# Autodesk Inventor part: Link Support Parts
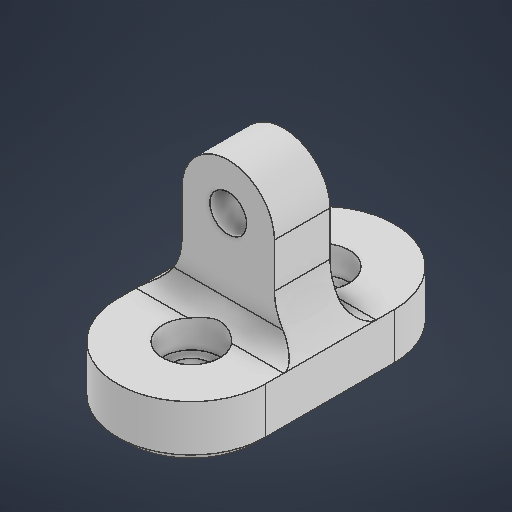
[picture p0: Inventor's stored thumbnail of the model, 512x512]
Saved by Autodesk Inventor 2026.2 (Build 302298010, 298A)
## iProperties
Created: 2026-05
Part Number: Link Support Parts
Material: 일반
Document SubType Name: Modeling
Designer: work
Density: 1 g/cm^3
Appearance: 기본값
Author: work
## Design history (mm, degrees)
sketch "스케치1"
  geometry: L1 (0, 7)-(0, -7); L2 (0, 7)-(0, -7); L3 (-8, 7)-(-8, -7); L4 (8, -7)-(8, 7); C1 r 2 at (0, 7); C2 r 2 at (0, -7); A1 r 8 centre (0, 7) between (8, 7) and (-8, 7); A2 r 8 centre (0, -7) between (-8, -7) and (8, -7); 2 further points
  constraints: 10 end point, 4 centre point, 4 point on circle, 4 tangent, 2 coincident, 2 equal length, 2 midpoint, 1 vertical
  dimensions: "d0" = 14 distance of L1.start L1.end; "d1" = 4 diameter of C1; "d2" = 4 diameter of C2; "d3" = 8 radius of A2
extrude "돌출1" new body sketch "스케치1" distance "d4" = 6; taper "d5" = 0 deg
sketch "스케치2"
  geometry: C1 r 2 at (0, -7) reference; C2 r 2 at (0, 7) reference; 3 further points
  constraints: 2 coincident
hole "구멍1" sketch "스케치2" at (0, -7), (0, 7) diameter "d6" = 4; stored, may be unused: countersink angle "d10" = 90 deg, drill point angle "d12" = 0 deg; dims "d7" = 5, "d8" = 6.2, "d9" = 3, "d11" = 5
sketch "스케치3"
  geometry: L1 (8, 6)-(-8, 6) reference; L2 (0, 6)-(0, 16); L3 (5, 6)-(5, 16); L4 (-5, 16)-(-5, 6); C1 r 2 at (0, 16); A1 r 5 centre (0, 6) between (-5, 6) and (5, 6); A2 r 5 centre (0, 16) between (5, 16) and (-5, 16); 2 further points
  constraints: 8 end point, 4 point on circle, 4 tangent, 3 centre point, 2 midpoint, 1 coincident, 1 parallel, 1 perpendicular
  dimensions: "d13" = 4 diameter of C1; "d14" = 10 distance of L2.start L2.end; "d15" = 5 radius of A2
extrude "돌출2" join sketch "스케치3" stored distance "d16" = 6; taper "d17" = 0 deg
fillet "모깎기1" dims "d18" = 6
fillet "모깎기2" dims "d19" = 2
chamfer "모따기1" distance "d20" = 1; stored, may be unused: second distance "d21" = 2, angle "d22" = 45 deg
node "솔리드1"
feature "A9D066F2-1C7D-4E18-AEED-F7BC21143FA4" dims "d6" = 4, "d7" = 5, "d8" = 6.2, "d9" = 3, "d10" = 90 deg, "d11" = 5, "d12" = 0
